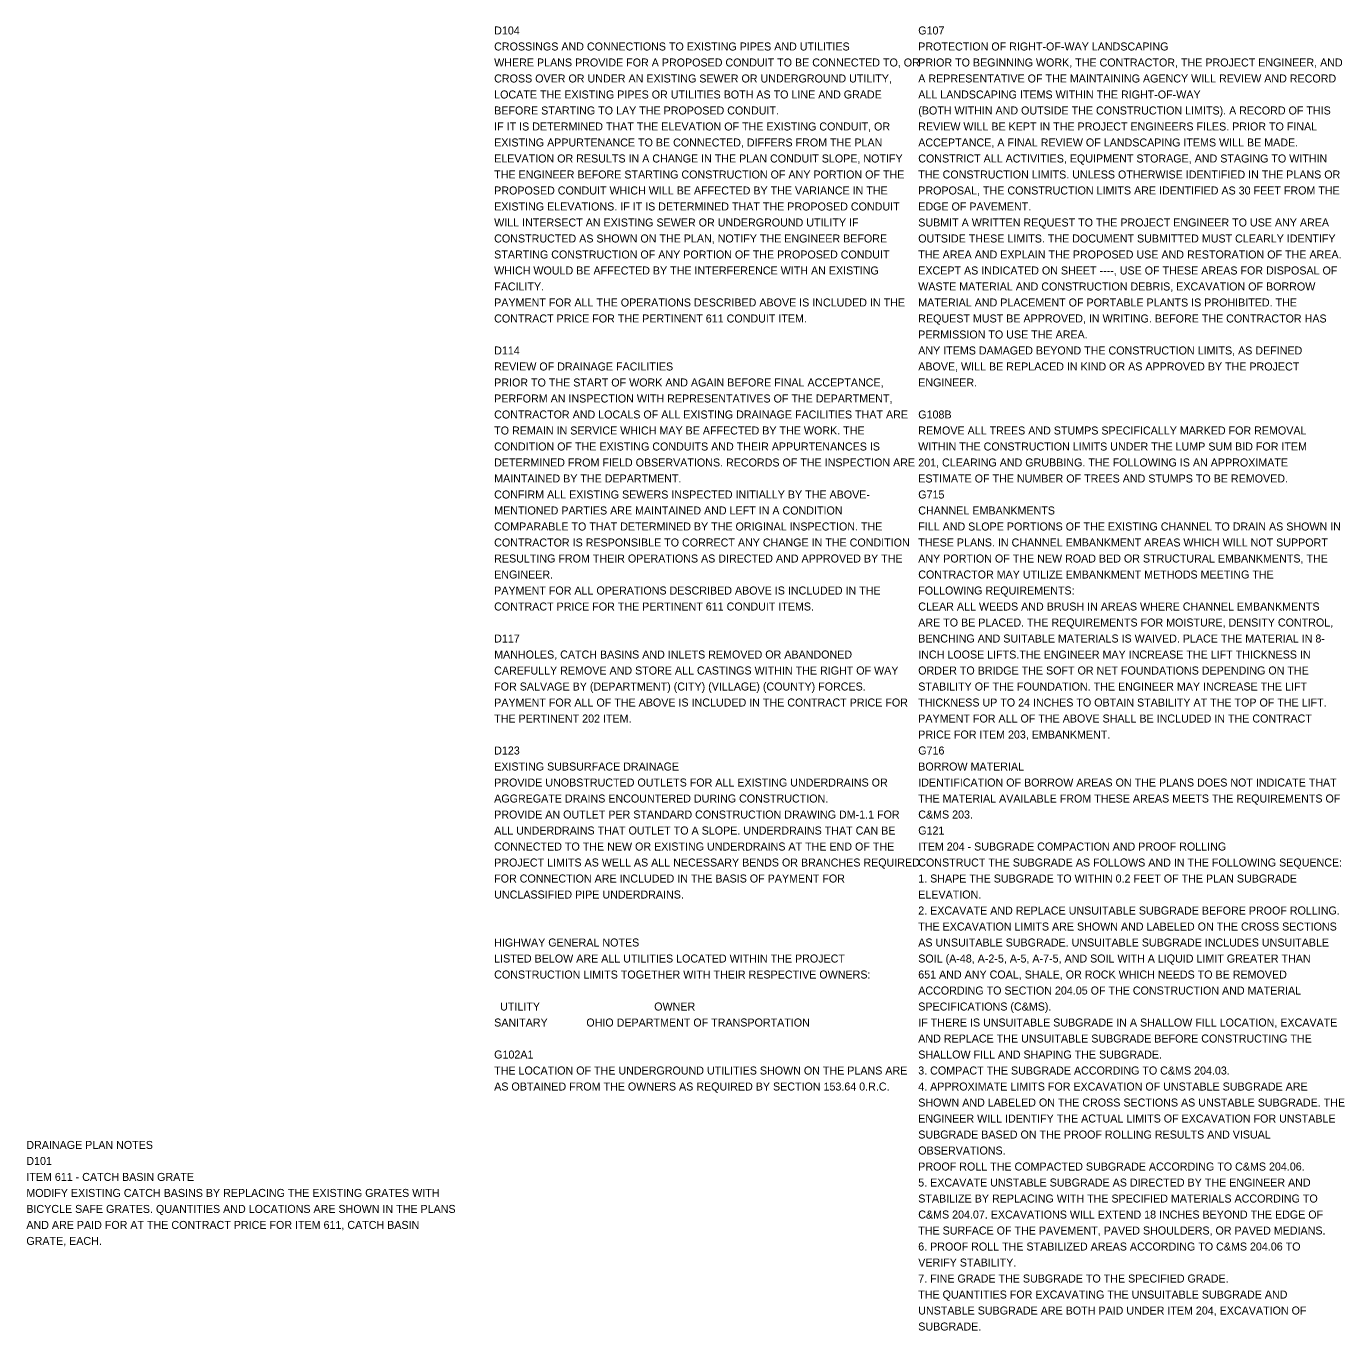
# Model space of a CAD drawing. Extents: x -19 to 64.6, y -1.7 to 22.
# Drawn here: x 41.55 to 64.62, y -1.68 to 21.14 of the extents above; entities that cross this region are included whole.
import ezdxf

# ---------------------------------------------------------------- set-up
doc = ezdxf.new("R2010")
doc.units = 0
doc.layers.add('SH_Text', color=7, linetype='Continuous')

msp = doc.modelspace()

# ---------------------------------------------------------------- texts
at = {"layer": 'SH_Text'}
for s, p in [('D104', (49.738, 21)), ('G107', (57.158, 21)), ('CROSSINGS AND CONNECTIONS TO EXISTING PIPES AND UTILITIES', (49.738, 20.72)), ('PROTECTION OF RIGHT-OF-WAY LANDSCAPING', (57.158, 20.72)), ('WHERE PLANS PROVIDE FOR A PROPOSED CONDUIT TO BE CONNECTED TO, OR ', (49.738, 20.44)), ('PRIOR TO BEGINNING WORK, THE CONTRACTOR, THE PROJECT ENGINEER, AND ', (57.158, 20.44)), ('CROSS OVER OR UNDER AN EXISTING SEWER OR UNDERGROUND UTILITY, ', (49.738, 20.16)), ('A REPRESENTATIVE OF THE MAINTAINING AGENCY WILL REVIEW AND RECORD ', (57.158, 20.16)), ('LOCATE THE EXISTING PIPES OR UTILITIES BOTH AS TO LINE AND GRADE ', (49.738, 19.88)), ('ALL LANDSCAPING ITEMS WITHIN THE RIGHT-OF-WAY', (57.158, 19.88)), ('BEFORE STARTING TO LAY THE PROPOSED CONDUIT.', (49.738, 19.6)), ('(BOTH WITHIN AND OUTSIDE THE CONSTRUCTION LIMITS). A RECORD OF THIS ', (57.158, 19.6)), ('IF IT IS DETERMINED THAT THE ELEVATION OF THE EXISTING CONDUIT, OR ', (49.738, 19.32)), ('REVIEW WILL BE KEPT IN THE PROJECT ENGINEERS FILES. PRIOR TO FINAL ', (57.158, 19.32)), ('EXISTING APPURTENANCE TO BE CONNECTED, DIFFERS FROM THE PLAN ', (49.738, 19.04)), ('ACCEPTANCE, A FINAL REVIEW OF LANDSCAPING ITEMS WILL BE MADE.', (57.158, 19.04)), ('ELEVATION OR RESULTS IN A CHANGE IN THE PLAN CONDUIT SLOPE, NOTIFY ', (49.738, 18.76)), ('CONSTRICT ALL ACTIVITIES, EQUIPMENT STORAGE, AND STAGING TO WITHIN ', (57.158, 18.76)), ('THE ENGINEER BEFORE STARTING CONSTRUCTION OF ANY PORTION OF THE ', (49.738, 18.48)), ('THE CONSTRUCTION LIMITS. UNLESS OTHERWISE IDENTIFIED IN THE PLANS OR ', (57.158, 18.48)), ('PROPOSED CONDUIT WHICH WILL BE AFFECTED BY THE VARIANCE IN THE ', (49.738, 18.2)), ('PROPOSAL, THE CONSTRUCTION LIMITS ARE IDENTIFIED AS 30 FEET FROM THE ', (57.158, 18.2)), ('EXISTING ELEVATIONS. IF IT IS DETERMINED THAT THE PROPOSED CONDUIT ', (49.738, 17.92)), ('EDGE OF PAVEMENT.', (57.158, 17.92)), ('WILL INTERSECT AN EXISTING SEWER OR UNDERGROUND UTILITY IF ', (49.738, 17.64)), ('SUBMIT A WRITTEN REQUEST TO THE PROJECT ENGINEER TO USE ANY AREA ', (57.158, 17.64)), ('CONSTRUCTED AS SHOWN ON THE PLAN, NOTIFY THE ENGINEER BEFORE ', (49.738, 17.36)), ('OUTSIDE THESE LIMITS. THE DOCUMENT SUBMITTED MUST CLEARLY IDENTIFY ', (57.158, 17.36)), ('STARTING CONSTRUCTION OF ANY PORTION OF THE PROPOSED CONDUIT ', (49.738, 17.08)), ('THE AREA AND EXPLAIN THE PROPOSED USE AND RESTORATION OF THE AREA. ', (57.158, 17.08)), ('WHICH WOULD BE AFFECTED BY THE INTERFERENCE WITH AN EXISTING ', (49.738, 16.8)), ('EXCEPT AS INDICATED ON SHEET ----, USE OF THESE AREAS FOR DISPOSAL OF ', (57.158, 16.8)), ('FACILITY.', (49.738, 16.52)), ('WASTE MATERIAL AND CONSTRUCTION DEBRIS, EXCAVATION OF BORROW ', (57.158, 16.52)), ('PAYMENT FOR ALL THE OPERATIONS DESCRIBED ABOVE IS INCLUDED IN THE ', (49.738, 16.24)), ('MATERIAL AND PLACEMENT OF PORTABLE PLANTS IS PROHIBITED. THE ', (57.158, 16.24)), ('CONTRACT PRICE FOR THE PERTINENT 611 CONDUIT ITEM.', (49.738, 15.96)), ('REQUEST MUST BE APPROVED, IN WRITING. BEFORE THE CONTRACTOR HAS ', (57.158, 15.96)), ('PERMISSION TO USE THE AREA.', (57.158, 15.68)), ('D114', (49.738, 15.4)), ('ANY ITEMS DAMAGED BEYOND THE CONSTRUCTION LIMITS, AS DEFINED ', (57.158, 15.4)), ('REVIEW OF DRAINAGE FACILITIES', (49.738, 15.12)), ('ABOVE, WILL BE REPLACED IN KIND OR AS APPROVED BY THE PROJECT ', (57.158, 15.12)), ('PRIOR TO THE START OF WORK AND AGAIN BEFORE FINAL ACCEPTANCE, ', (49.738, 14.84)), ('ENGINEER.', (57.158, 14.84)), ('PERFORM AN INSPECTION WITH REPRESENTATIVES OF THE DEPARTMENT, ', (49.738, 14.56)), ('CONTRACTOR AND LOCALS OF ALL EXISTING DRAINAGE FACILITIES THAT ARE ', (49.738, 14.28)), ('G108B', (57.158, 14.28)), ('TO REMAIN IN SERVICE WHICH MAY BE AFFECTED BY THE WORK. THE ', (49.738, 14)), ('REMOVE ALL TREES AND STUMPS SPECIFICALLY MARKED FOR REMOVAL ', (57.158, 14)), ('CONDITION OF THE EXISTING CONDUITS AND THEIR APPURTENANCES IS ', (49.738, 13.72)), ('WITHIN THE CONSTRUCTION LIMITS UNDER THE LUMP SUM BID FOR ITEM ', (57.158, 13.72)), ('DETERMINED FROM FIELD OBSERVATIONS. RECORDS OF THE INSPECTION ARE ', (49.738, 13.44)), ('201, CLEARING AND GRUBBING. THE FOLLOWING IS AN APPROXIMATE ', (57.158, 13.44)), ('MAINTAINED BY THE DEPARTMENT.', (49.738, 13.16)), ('ESTIMATE OF THE NUMBER OF TREES AND STUMPS TO BE REMOVED.', (57.158, 13.16)), ('CONFIRM ALL EXISTING SEWERS INSPECTED INITIALLY BY THE ABOVE-', (49.738, 12.88)), ('G715', (57.158, 12.88)), ('MENTIONED PARTIES ARE MAINTAINED AND LEFT IN A CONDITION ', (49.738, 12.6)), ('CHANNEL EMBANKMENTS', (57.158, 12.6)), ('COMPARABLE TO THAT DETERMINED BY THE ORIGINAL INSPECTION. THE ', (49.738, 12.32)), ('FILL AND SLOPE PORTIONS OF THE EXISTING CHANNEL TO DRAIN AS SHOWN IN ', (57.158, 12.32)), ('CONTRACTOR IS RESPONSIBLE TO CORRECT ANY CHANGE IN THE CONDITION ', (49.738, 12.04)), ('THESE PLANS. IN CHANNEL EMBANKMENT AREAS WHICH WILL NOT SUPPORT ', (57.158, 12.04)), ('RESULTING FROM THEIR OPERATIONS AS DIRECTED AND APPROVED BY THE ', (49.738, 11.76)), ('ANY PORTION OF THE NEW ROAD BED OR STRUCTURAL EMBANKMENTS, THE ', (57.158, 11.76)), ('ENGINEER.', (49.738, 11.48)), ('CONTRACTOR MAY UTILIZE EMBANKMENT METHODS MEETING THE ', (57.158, 11.48)), ('PAYMENT FOR ALL OPERATIONS DESCRIBED ABOVE IS INCLUDED IN THE ', (49.738, 11.2)), ('FOLLOWING REQUIREMENTS:', (57.158, 11.2)), ('CONTRACT PRICE FOR THE PERTINENT 611 CONDUIT ITEMS.', (49.738, 10.92)), ('CLEAR ALL WEEDS AND BRUSH IN AREAS WHERE CHANNEL EMBANKMENTS ', (57.158, 10.92)), ('ARE TO BE PLACED. THE REQUIREMENTS FOR MOISTURE, DENSITY CONTROL, ', (57.158, 10.64)), ('D117', (49.738, 10.36)), ('BENCHING AND SUITABLE MATERIALS IS WAIVED. PLACE THE MATERIAL IN 8-', (57.158, 10.36)), ('MANHOLES, CATCH BASINS AND INLETS REMOVED OR ABANDONED', (49.738, 10.08)), ('INCH LOOSE LIFTS.THE ENGINEER MAY INCREASE THE LIFT THICKNESS IN ', (57.158, 10.08)), ('CAREFULLY REMOVE AND STORE ALL CASTINGS WITHIN THE RIGHT OF WAY ', (49.738, 9.8)), ('ORDER TO BRIDGE THE SOFT OR NET FOUNDATIONS DEPENDING ON THE ', (57.158, 9.8)), ('FOR SALVAGE BY (DEPARTMENT) (CITY) (VILLAGE) (COUNTY) FORCES.', (49.738, 9.52)), ('STABILITY OF THE FOUNDATION. THE ENGINEER MAY INCREASE THE LIFT ', (57.158, 9.52)), ('PAYMENT FOR ALL OF THE ABOVE IS INCLUDED IN THE CONTRACT PRICE FOR ', (49.738, 9.24)), ('THICKNESS UP TO 24 INCHES TO OBTAIN STABILITY AT THE TOP OF THE LIFT. ', (57.158, 9.24)), ('THE PERTINENT 202 ITEM.', (49.738, 8.96)), ('PAYMENT FOR ALL OF THE ABOVE SHALL BE INCLUDED IN THE CONTRACT ', (57.158, 8.96)), ('PRICE FOR ITEM 203, EMBANKMENT.', (57.158, 8.68)), ('D123', (49.738, 8.4)), ('G716', (57.158, 8.4)), ('EXISTING SUBSURFACE DRAINAGE', (49.738, 8.12)), ('BORROW MATERIAL', (57.158, 8.12)), ('PROVIDE UNOBSTRUCTED OUTLETS FOR ALL EXISTING UNDERDRAINS OR', (49.738, 7.84)), ('IDENTIFICATION OF BORROW AREAS ON THE PLANS DOES NOT INDICATE THAT ', (57.158, 7.84)), ('AGGREGATE DRAINS ENCOUNTERED DURING CONSTRUCTION.', (49.738, 7.56)), ('THE MATERIAL AVAILABLE FROM THESE AREAS MEETS THE REQUIREMENTS OF ', (57.158, 7.56)), ('PROVIDE AN OUTLET PER STANDARD CONSTRUCTION DRAWING DM-1.1 FOR ', (49.738, 7.28)), ('C&MS 203.', (57.158, 7.28)), ('ALL UNDERDRAINS THAT OUTLET TO A SLOPE. UNDERDRAINS THAT CAN BE ', (49.738, 7)), ('G121', (57.158, 7)), ('CONNECTED TO THE NEW OR EXISTING UNDERDRAINS AT THE END OF THE ', (49.738, 6.72)), ('ITEM 204 - SUBGRADE COMPACTION AND PROOF ROLLING', (57.158, 6.72)), ('PROJECT LIMITS AS WELL AS ALL NECESSARY BENDS OR BRANCHES REQUIRED ', (49.738, 6.44)), ('CONSTRUCT THE SUBGRADE AS FOLLOWS AND IN THE FOLLOWING SEQUENCE:', (57.158, 6.44)), ('FOR CONNECTION ARE INCLUDED IN THE BASIS OF PAYMENT FOR ', (49.738, 6.16)), ('1. SHAPE THE SUBGRADE TO WITHIN 0.2 FEET OF THE PLAN SUBGRADE ', (57.158, 6.16)), ('UNCLASSIFIED PIPE UNDERDRAINS.', (49.738, 5.88)), ('ELEVATION.', (57.158, 5.88)), ('2. EXCAVATE AND REPLACE UNSUITABLE SUBGRADE BEFORE PROOF ROLLING. ', (57.158, 5.6)), ('THE EXCAVATION LIMITS ARE SHOWN AND LABELED ON THE CROSS SECTIONS ', (57.158, 5.32)), ('HIGHWAY GENERAL NOTES', (49.738, 5.04)), ('AS UNSUITABLE SUBGRADE. UNSUITABLE SUBGRADE INCLUDES UNSUITABLE ', (57.158, 5.04)), ('LISTED BELOW ARE ALL UTILITIES LOCATED WITHIN THE PROJECT ', (49.738, 4.76)), ('SOIL (A-48, A-2-5, A-5, A-7-5, AND SOIL WITH A LIQUID LIMIT GREATER THAN ', (57.158, 4.76)), ('CONSTRUCTION LIMITS TOGETHER WITH THEIR RESPECTIVE OWNERS:', (49.738, 4.48)), ('651 AND ANY COAL, SHALE, OR ROCK WHICH NEEDS TO BE REMOVED ', (57.158, 4.48)), ('ACCORDING TO SECTION 204.05 OF THE CONSTRUCTION AND MATERIAL ', (57.158, 4.2)), ('  UTILITY', (49.738, 3.92)), ('OWNER', (52.538, 3.92)), ('SPECIFICATIONS (C&MS).', (57.158, 3.92)), ('SANITARY             OHIO DEPARTMENT OF TRANSPORTATION', (49.738, 3.64)), ('IF THERE IS UNSUITABLE SUBGRADE IN A SHALLOW FILL LOCATION, EXCAVATE ', (57.158, 3.64)), ('AND REPLACE THE UNSUITABLE SUBGRADE BEFORE CONSTRUCTING THE ', (57.158, 3.36)), ('G102A1', (49.738, 3.08)), ('SHALLOW FILL AND SHAPING THE SUBGRADE. ', (57.158, 3.08)), ('THE LOCATION OF THE UNDERGROUND UTILITIES SHOWN ON THE PLANS ARE ', (49.738, 2.8)), ('3. COMPACT THE SUBGRADE ACCORDING TO C&MS 204.03.', (57.158, 2.8)), ('AS OBTAINED FROM THE OWNERS AS REQUIRED BY SECTION 153.64 0.R.C.', (49.738, 2.52)), ('4. APPROXIMATE LIMITS FOR EXCAVATION OF UNSTABLE SUBGRADE ARE ', (57.158, 2.52)), ('SHOWN AND LABELED ON THE CROSS SECTIONS AS UNSTABLE SUBGRADE. THE ', (57.158, 2.24)), ('ENGINEER WILL IDENTIFY THE ACTUAL LIMITS OF EXCAVATION FOR UNSTABLE ', (57.158, 1.96)), ('DRAINAGE PLAN NOTES', (41.552, 1.498)), ('SUBGRADE BASED ON THE PROOF ROLLING RESULTS AND VISUAL ', (57.158, 1.68)), ('OBSERVATIONS.', (57.158, 1.4)), ('D101', (41.552, 1.218)), ('PROOF ROLL THE COMPACTED SUBGRADE ACCORDING TO C&MS 204.06.', (57.158, 1.12)), ('ITEM 611 - CATCH BASIN GRATE', (41.552, 0.938)), ('5. EXCAVATE UNSTABLE SUBGRADE AS DIRECTED BY THE ENGINEER AND ', (57.158, 0.84)), ('MODIFY EXISTING CATCH BASINS BY REPLACING THE EXISTING GRATES WITH', (41.552, 0.658)), ('STABILIZE BY REPLACING WITH THE SPECIFIED MATERIALS ACCORDING TO ', (57.158, 0.56)), ('BICYCLE SAFE GRATES. QUANTITIES AND LOCATIONS ARE SHOWN IN THE PLANS', (41.552, 0.378)), ('AND ARE PAID FOR AT THE CONTRACT PRICE FOR ITEM 611, CATCH BASIN ', (41.552, 0.098)), ('C&MS 204.07. EXCAVATIONS WILL EXTEND 18 INCHES BEYOND THE EDGE OF ', (57.158, 0.28)), ('THE SURFACE OF THE PAVEMENT, PAVED SHOULDERS, OR PAVED MEDIANS.', (57.158, 0)), ('GRATE, EACH.', (41.552, -0.182)), ('6. PROOF ROLL THE STABILIZED AREAS ACCORDING TO C&MS 204.06 TO ', (57.158, -0.28)), ('VERIFY STABILITY. ', (57.158, -0.56)), ('7. FINE GRADE THE SUBGRADE TO THE SPECIFIED GRADE.', (57.158, -0.84)), ('THE QUANTITIES FOR EXCAVATING THE UNSUITABLE SUBGRADE AND ', (57.158, -1.12)), ('UNSTABLE SUBGRADE ARE BOTH PAID UNDER ITEM 204, EXCAVATION OF ', (57.158, -1.4)), ('SUBGRADE.', (57.158, -1.68))]:
    msp.add_text(s, height=0.14, dxfattribs=at).set_placement(p)

doc.saveas('drawing.dxf')
